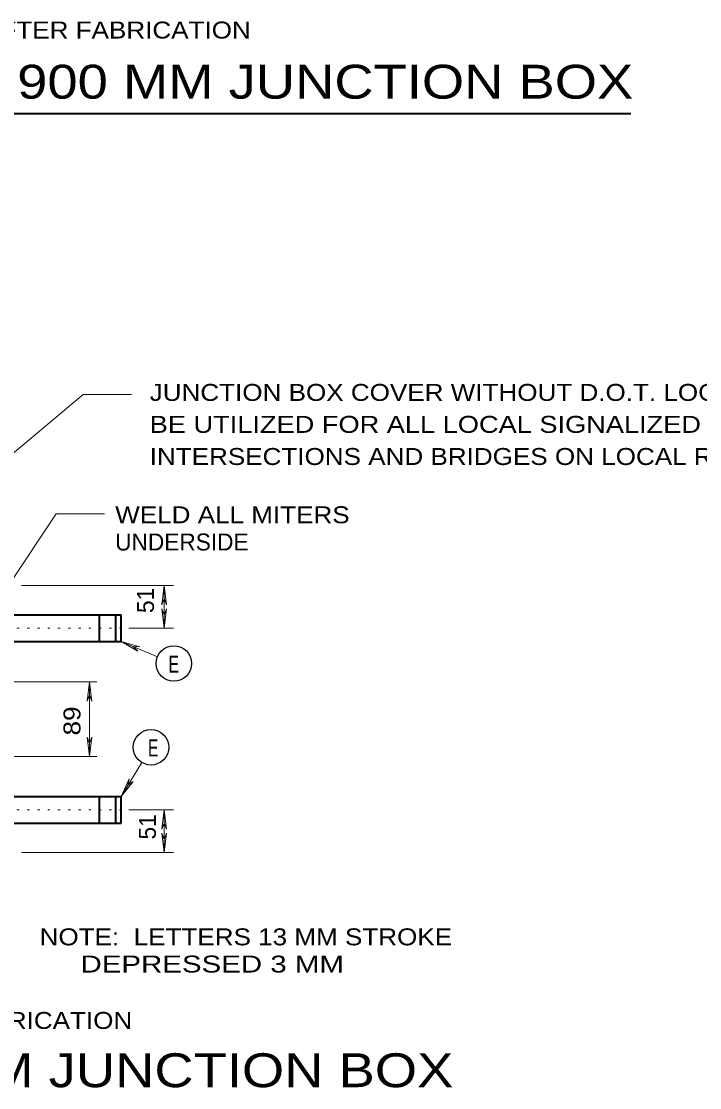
# Model space of a CAD drawing. Extents: x 312583 to 312854, y 144419 to 144597.
# Drawn here: x 312683.17 to 312713.61, y 144489.61 to 144537.44 of the extents above; entities that cross this region are included whole.
import ezdxf
from ezdxf.enums import TextEntityAlignment as Align

# ---------------------------------------------------------------- set-up
doc = ezdxf.new("R2010")
doc.units = 0
doc.header["$LTSCALE"] = 0.3
doc.linetypes.add('DOTTED', pattern=[1.5, 0.3, -1.2])
doc.layers.add('1', color=7, linetype='Continuous', lineweight=13)

msp = doc.modelspace()

# ---------------------------------------------------------------- linework, layer by layer
at = {"layer": '1', "lineweight": 40}
for p, q in [((312637.3201, 144533.3146), (312710.5195, 144533.3146)), ((312682.6108, 144510.8206), (312687.6401, 144510.8206)), ((312686.6818, 144509.6246), (312686.6818, 144510.8206)), ((312687.4025, 144509.6246), (312687.4025, 144510.8206)), ((312687.6401, 144509.6246), (312687.6401, 144510.8206)), ((312682.6108, 144509.6246), (312687.6401, 144509.6246)), ((312682.6108, 144502.671), (312687.6401, 144502.671)), ((312686.6818, 144501.475), (312686.6818, 144502.671)), ((312687.4025, 144501.475), (312687.4025, 144502.671)), ((312687.6401, 144501.475), (312687.6401, 144502.671)), ((312682.6108, 144501.475), (312687.6401, 144501.475))]:
    msp.add_line(p, q, dxfattribs=at)
at = {"layer": '1'}
for p, q in [((312683.1705, 144512.1393), (312690.0015, 144512.1393)), ((312689.5798, 144512.1393), (312689.4725, 144511.273)), ((312689.5798, 144512.1393), (312689.5798, 144510.2226)), ((312689.5798, 144512.1393), (312689.6871, 144511.273)), ((312689.4725, 144511.273), (312689.5798, 144511.549)), ((312689.6871, 144511.273), (312689.5798, 144511.549)), ((312689.4725, 144511.089), (312689.5798, 144510.813)), ((312689.5798, 144510.2226), (312689.4725, 144511.089)), ((312689.6871, 144511.089), (312689.5798, 144510.813)), ((312689.5798, 144510.2226), (312689.6871, 144511.089)), ((312687.9851, 144510.2226), (312690.0015, 144510.2226)), ((312689.2808, 144508.9423), (312687.6401, 144509.6246)), ((312687.6401, 144509.6246), (312688.3991, 144509.1876)), ((312687.6401, 144509.6246), (312688.4835, 144509.387)), ((312688.3991, 144509.1876), (312688.1845, 144509.3946)), ((312688.4835, 144509.387), (312688.1845, 144509.3946)), ((312677.3208, 144507.823), (312686.5515, 144507.823)), ((312686.2295, 144507.823), (312686.1221, 144506.9566)), ((312686.2295, 144504.4726), (312686.2295, 144507.823)), ((312686.2295, 144507.823), (312686.3368, 144506.9566)), ((312686.1221, 144506.9566), (312686.2295, 144507.2326)), ((312686.3368, 144506.9566), (312686.2295, 144507.2326)), ((312686.1221, 144505.339), (312686.2295, 144505.063)), ((312686.2295, 144504.4726), (312686.1221, 144505.339)), ((312686.3368, 144505.339), (312686.2295, 144505.063)), ((312686.2295, 144504.4726), (312686.3368, 144505.339)), ((312677.3208, 144504.4726), (312686.5515, 144504.4726)), ((312688.5755, 144504.2043), (312687.6401, 144502.671)), ((312687.6401, 144502.671), (312688.0005, 144503.4683)), ((312688.0005, 144503.4683), (312687.9468, 144503.177)), ((312687.6401, 144502.671), (312688.1845, 144503.3533)), ((312688.1845, 144503.3533), (312687.9468, 144503.177)), ((312687.9851, 144502.073), (312690.0015, 144502.073)), ((312689.5798, 144502.073), (312689.4725, 144501.2066)), ((312689.5798, 144500.1563), (312689.5798, 144502.073)), ((312689.5798, 144502.073), (312689.6871, 144501.2066)), ((312689.4725, 144501.2066), (312689.5798, 144501.4826)), ((312689.6871, 144501.2066), (312689.5798, 144501.4826)), ((312689.4725, 144501.0226), (312689.5798, 144500.7466)), ((312689.5798, 144500.1563), (312689.4725, 144501.0226)), ((312689.6871, 144501.0226), (312689.5798, 144500.7466)), ((312689.5798, 144500.1563), (312689.6871, 144501.0226)), ((312683.1705, 144500.1563), (312690.0015, 144500.1563))]:
    msp.add_line(p, q, dxfattribs=at)
at = {"layer": '1', "linetype": 'DOTTED'}
for p, q in [((312681.5911, 144510.2226), (312687.9851, 144510.2226)), ((312681.5911, 144502.073), (312687.9851, 144502.073))]:
    msp.add_line(p, q, dxfattribs=at)
at = {"layer": '1'}
for points in [[(312669.0408, 144506.535), (312685.9458, 144520.703), (312688.1155, 144520.703)], [(312686.9041, 144515.3516), (312684.7345, 144515.3516), (312682.5955, 144512.1393)]]:
    msp.add_lwpolyline(points, dxfattribs=at)
at = {"layer": '1', "lineweight": 25}
for centre in [(312690.013, 144508.6395), (312688.9866, 144504.8809)]:
    msp.add_circle(centre, 0.7964, dxfattribs=at)

# ---------------------------------------------------------------- texts
at = {"layer": '1'}
for s, width, p in [('ANCHORS TO BE HOT DIPPED GALV. AFTER FABRICATION', 1.15, (312660.2146, 144536.6706)), ('JUNCTION BOX COVER WITHOUT D.O.T. LOGO SHALL', 1.15, (312688.9281, 144520.4183)), ('BE UTILIZED FOR ALL LOCAL SIGNALIZED', 1.2, (312688.9281, 144518.9846)), ('INTERSECTIONS AND BRIDGES ON LOCAL ROADS.', 1.15, (312688.9281, 144517.5433)), ('WELD ALL MITERS', 1.15, (312687.3795, 144514.929)), ('E', 0.7, (312689.7676, 144508.2302)), ('E', 0.7, (312688.8466, 144504.4736)), ('NOTE:  LETTERS 13 MM STROKE', 1.15, (312683.9876, 144495.9989)), ('     DEPRESSED 3 MM', 1.3, (312683.9876, 144494.7789)), ('ANCHORS TO BE HOT DIPPED GALV. AFTER FABRICATION', 1.15, (312654.8958, 144492.25))]:
    msp.add_text(s, height=0.76, dxfattribs=dict(at, width=width)).set_placement(p)
at = {"layer": '1', "width": 1.2}
for s, p in [('PLAN-FRAME AND COVER FOR 450 BY 900 MM JUNCTION BOX', (312673.7634, 144533.9741)), ('PLAN-FRAME AND COVER FOR 250 BY 900 MM JUNCTION BOX', (312665.6882, 144489.6359))]:
    msp.add_text(s, height=1.52, dxfattribs=at).set_placement(p, align=Align.CENTER)
at = {"layer": '1'}
msp.add_text('UNDERSIDE', height=0.76, dxfattribs=at).set_placement((312687.3795, 144513.709))
for p in [(312689.1184, 144510.9032), (312689.2043, 144500.7453)]:
    msp.add_text('51 ', height=0.76, rotation=90, dxfattribs=at).set_placement(p)
at = {"layer": '1', "width": 1.15}
msp.add_text('89 ', height=0.76, rotation=90, dxfattribs=at).set_placement((312685.8188, 144505.4121))

doc.saveas('drawing.dxf')
